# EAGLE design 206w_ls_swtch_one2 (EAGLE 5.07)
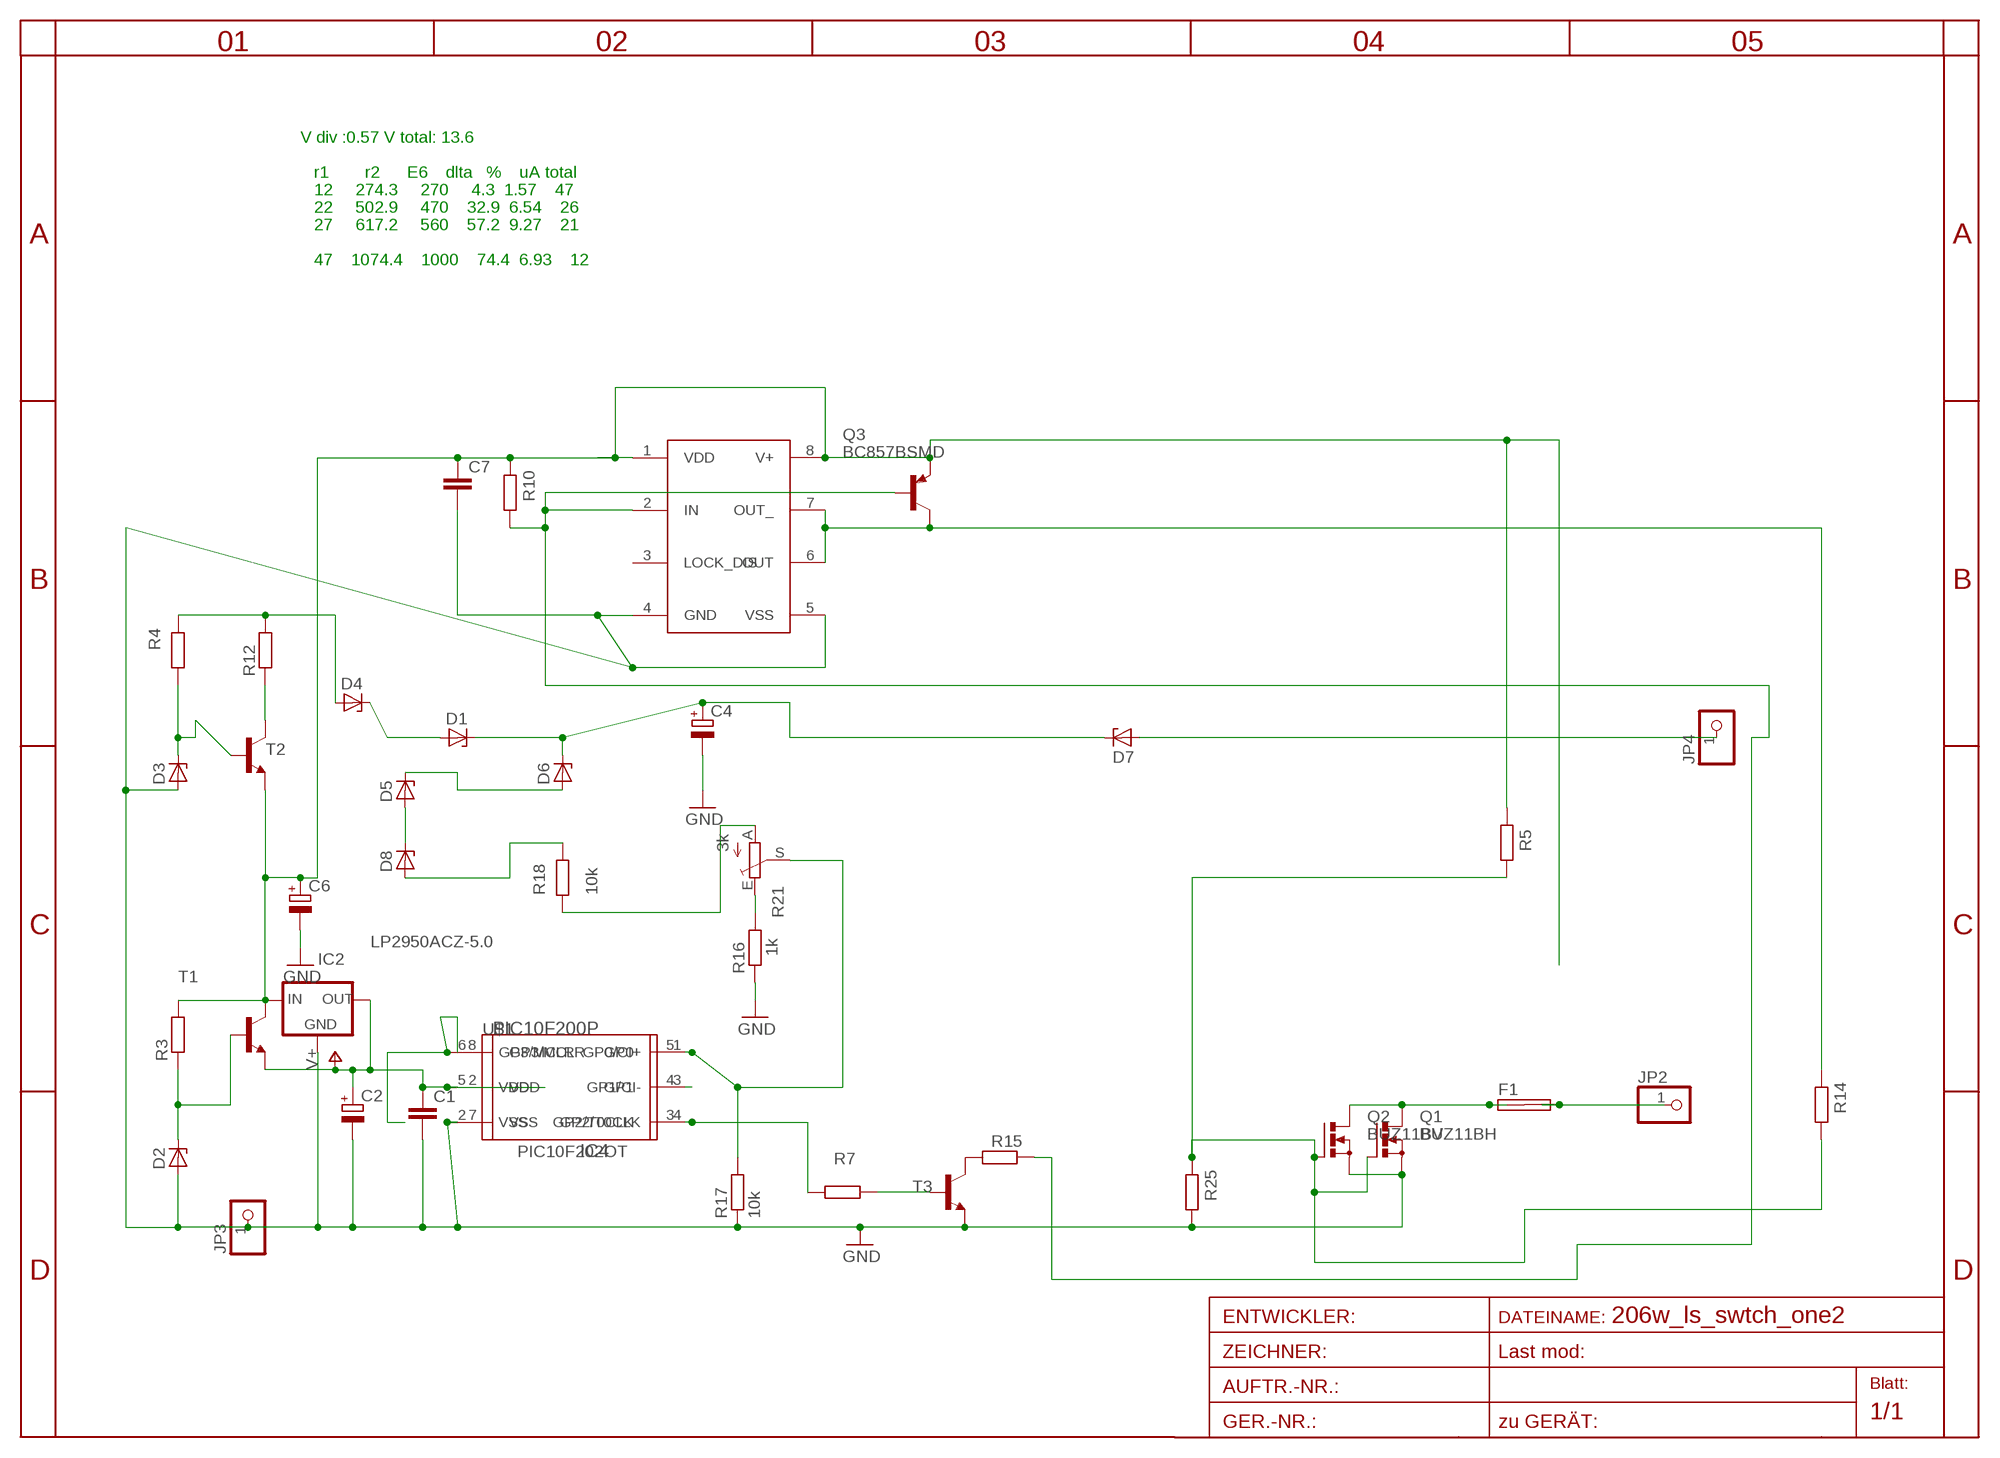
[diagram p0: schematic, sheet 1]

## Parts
C1  C-EUC1206  [C1206]
C2  CPOL-EUSANYO_SMD_E12  [SANYO-OSCON_SMD_E12]
C4  CPOL-EUE5-8.5  [E5-8,5]
C6  CPOL-EUSANYO_SMD_E12  [SANYO-OSCON_SMD_E12]
C7  C-EUC1206  [C1206]
D1  ZENER-DIODESMB  [SMB]
D2  ZENER-DIODESOD80C  [SOD80C]
D3  ZENER-DIODESMB  [SMB]
D4  ZENER-DIODESMB  [SMB]
D5  ZENER-DIODESMB  [SMB]
D6  ZENER-DIODESMB  [SMB]
D7  ZENER-DIODESMB  [SMB]
D8  ZENER-DIODESMB  [SMB]
F1  SHK20L7MM5  [7MM5]
IC2  LP2950ACZ-5.0  [TO92]
IC3  TC4432X  [SO-08]
IC4  PIC10F200P  [DIL8]
JP2  PINHD-1X11MM6  [1X1MM8]
JP3  PINHD-1X11MM6  [1X1MM8]
JP4  PINHD-1X11MM6  [1X1MM8]
Q1  BUZ11BH  [TO220BH]
Q2  BUZ11BV  [TO220BV]
Q3  BC857BSMD  [SOT23-BEC]
R3  R-EU_R0805  [R0805]
R4  R-EU_R0805  [R0805]
R5  R-EU_R0805  [R0805]
R7  R-EU_R0805  [R0805]
R10  R-EU_R0805  [R0805]
R12  R-EU_R0805  [R0805]
R14  R-EU_R0805  [R0805]
R15  R-EU_R0805  [R0805]
R16  1k  R-EU_R0805  [R0805]
R17  10k  R-EU_R0805  [R0805]
R18  10k  R-EU_R1206  [R1206]
R21  3k  TRIM_EU-CA6V  [CA6V]
R25  R-EU_R0805  [R0805]
T1  BC846BLT1-NPN-SOT23-BEC  [SOT23-BEC]
T2  BC846BLT1-NPN-SOT23-BEC  [SOT23-BEC]
T3  BC846BLT1-NPN-SOT23-BEC  [SOT23-BEC]
U$1  PIC10F202OT  [SOT23-6]

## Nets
BB: IC3.2(IN) Q3.B R10.1 R15.2
DRAIN: F1.1A F1.1B Q1.D Q2.D
GND: C1.2 C2.- C4.- C6.- C7.2 D2.A D3.A IC2.2(GND) IC3.4(GND) IC3.5(VSS) IC4.7(VSS) JP3.1 Q1.S Q2.S R16.1 R17.1 R25.1 T3.E U$1.2(VSS)
IN+: D7.A JP4.1
N$1: IC4.5(GP0) R17.2 R21.S U$1.1(GP0/CI+)
N$2: IC4.8(GP3/MCLR) U$1.6(GP3/MCLR)
N$3: Q1.G Q2.G R5.1 R14.1 R25.2
N$4: R18.1 R21.A
N$5: R16.2 R21.E
N$6: D2.C R3.1 T1.B
N$9: IC4.3(GP2/T0CLK) R7.1 U$1.4(GP2/T0CLK)
N$10: D5.C D6.A
N$11: IC3.6(OUT) IC3.7(OUT_) Q3.C R14.2
N$12: D3.C R4.1 T2.B
N$16: R12.1 T2.C
N$17: D5.A D8.C
N$18: D1.A D4.C
N$19: D8.A R18.2
N$21: D4.A R4.2 R12.2
N$25: IC4.4(GP1) U$1.3(GP1/CI-)
N$26: R7.2 T3.B
N$31: R15.1 T3.C
OUT-: F1.2A F1.2B JP2.1
V60: C4.+ D1.C D6.C D7.C
V+: C1.1 C2.+ IC2.1(OUT) IC4.2(VDD) T1.E U$1.5(VDD)
VCC: C6.+ C7.1 IC2.3(IN) IC3.1(VDD) IC3.8(V+) Q3.E R3.2 R5.2 R10.2 T1.C T2.E
Unconnected: IC3.3(LOCK_DIS)

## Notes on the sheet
- V div :0.57 V total: 13.6
- r1        r2      E6    dlta   %    uA total
- 12     274.3     270     4.3  1.57    47
- 22     502.9     470    32.9  6.54    26
- 27     617.2     560    57.2  9.27    21
- 47    1074.4    1000    74.4  6.93    12

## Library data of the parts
C1 C7 = rcl:C-EU: CAPACITOR, European symbol
C2 C4 C6 = rcl:CPOL-EU: POLARIZED CAPACITOR, European symbol
D1-D8 = diode-1:ZENER-DIODE: Z-Diode
F1 = fuse:SHK20L: FUSE HOLDER 5 x 20 mm, SH contact, SHH1 Schukat, E1073 Buerklin
IC2 = v-reg:LP2950?*: Source: http://cache.national.com/ds/LP/LP2950.pdf
IC3 = microchip:TC4432
IC4 = microchip-5:PIC10F20*: uPC nW 0,25/0,5k Program Flash memory
JP2-JP4 = pinhead:PINHD-1X1: PIN HEADER
Q1 Q2 = transistor-power:BUZ11: N-CHANNEL MOS FET
Q3 = transistor-pnp:BC857*: PNP Transistror
R3-R5 R10 R12 R14-R16 R25 = rcl:R-EU_: RESISTOR, European symbol
R7 R17 R18 = rcl-2:R-EU_: RESISTOR, European symbol
R21 = pot:TRIM_EU-: POTENTIOMETER
T1-T3 = transistor-neu-to92:*-NPN-: NPN Transistror
U$1 = microchip-5:PIC10F2*: uPC nW 0,25/0,5k Program Flash memory Comparator

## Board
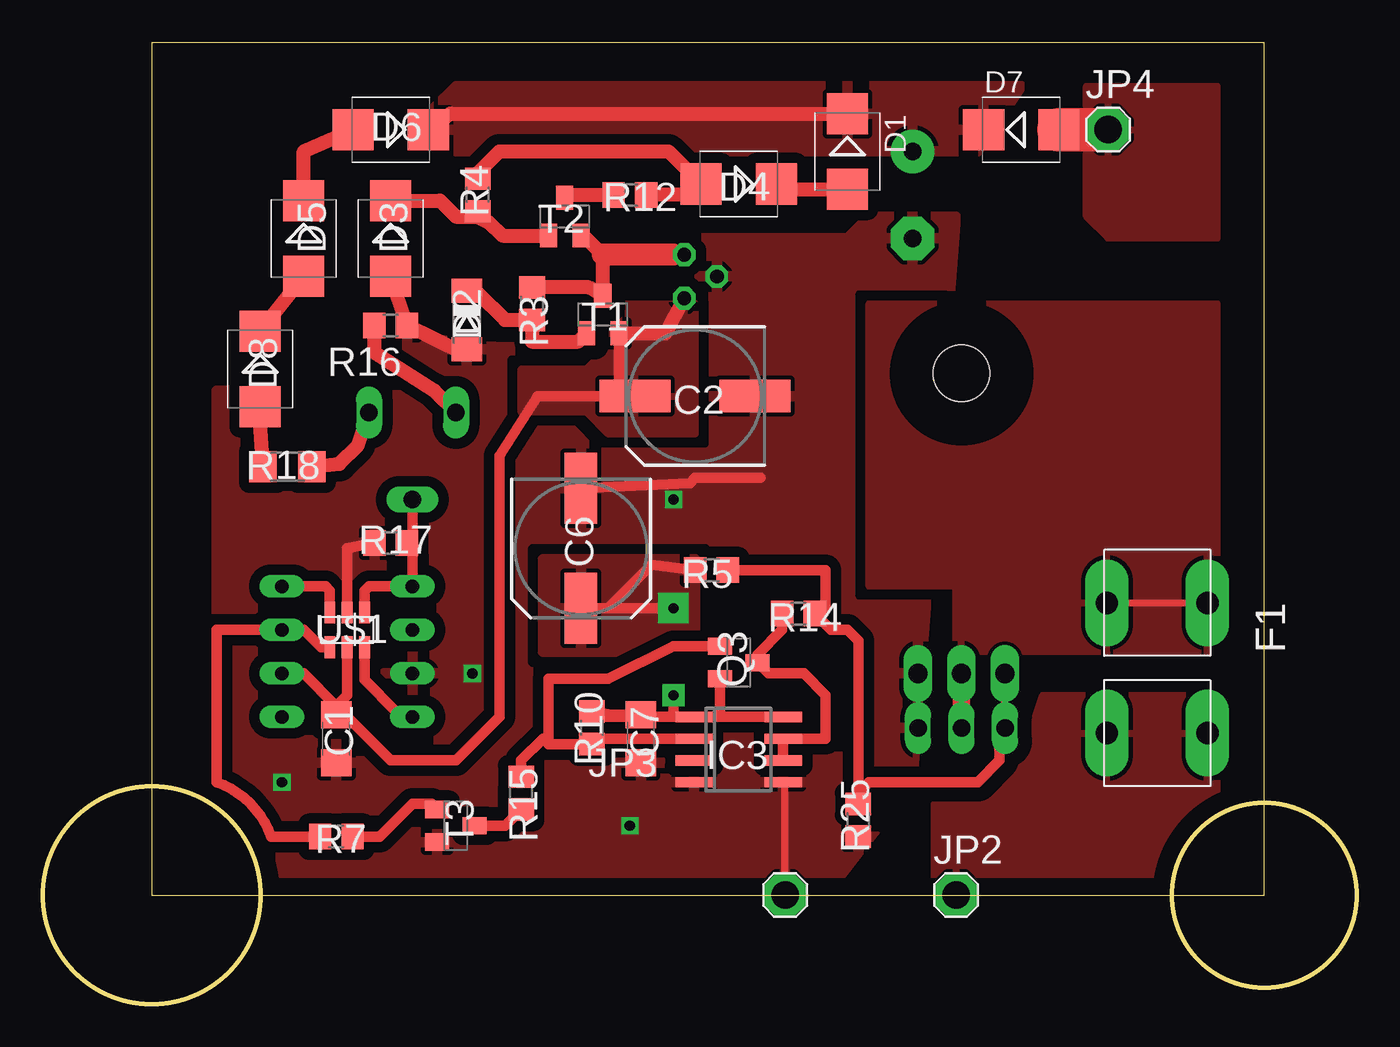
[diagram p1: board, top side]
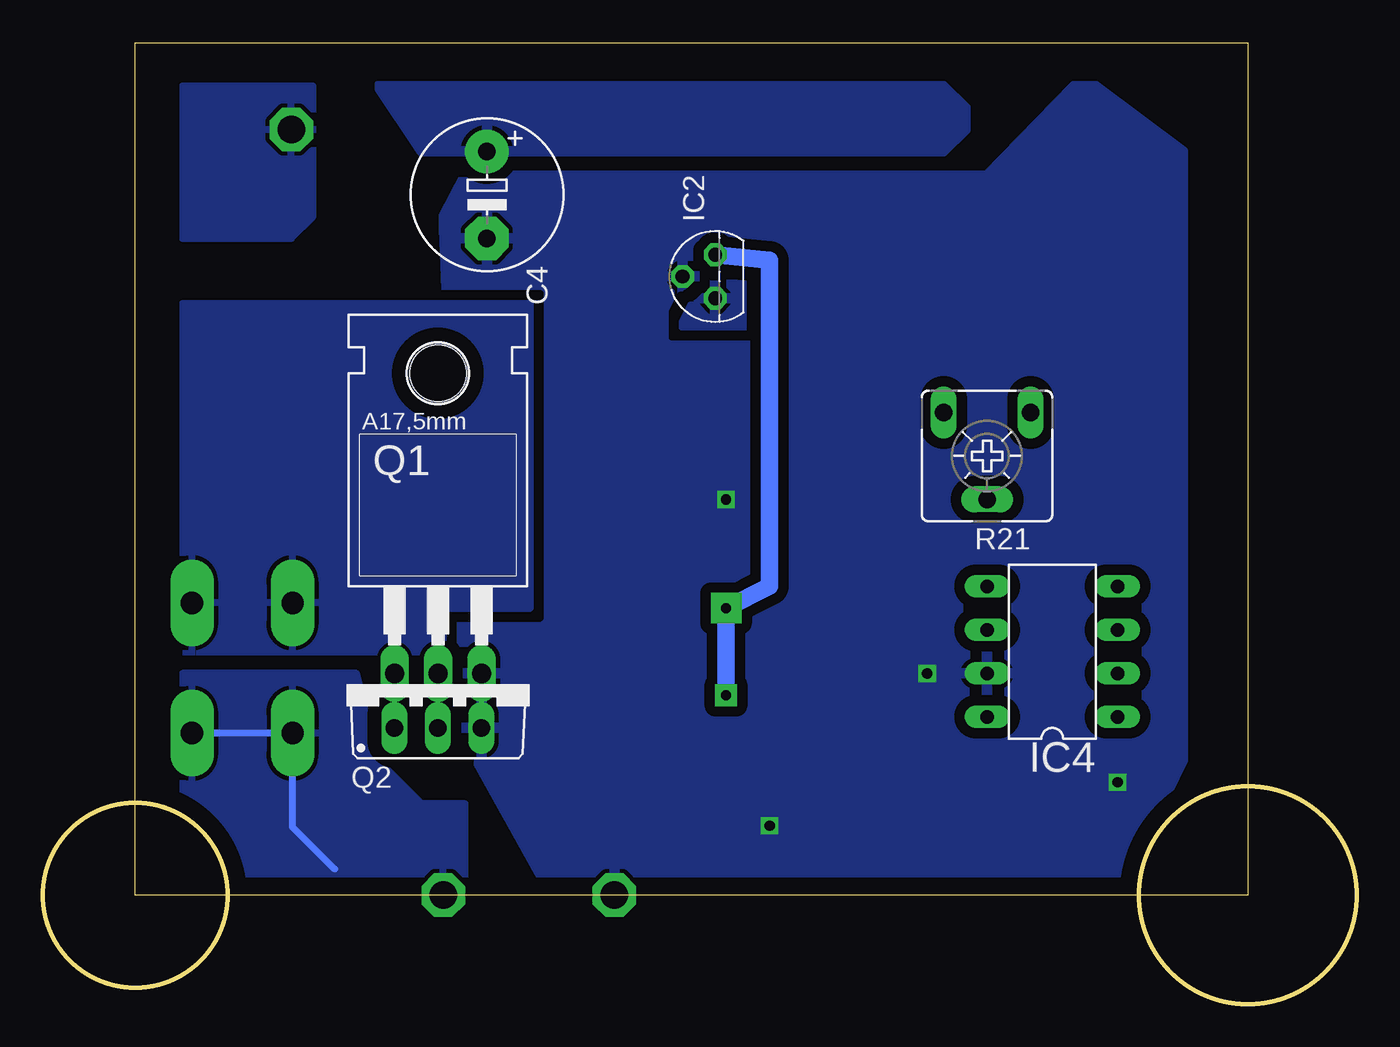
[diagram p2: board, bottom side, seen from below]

Size 76.74 x 56.11 mm. Coordinates in mm from the lower left corner, seen from the top.
Outline: 6.35,6.35 71.35,6.35 71.35,56.11 6.35,56.11 6.35,6.35
Outline: circle at 71.35,6.35 radius 5.39
Outline: circle at 6.35,6.35 radius 6.35
Copper layers (1*16): Top 0.035mm / dielectric 1.5mm / Bottom 0.035mm
Design rules "default": minimum track width 10mil, minimum drill 24mil, track to track 8mil, track to pad 8mil, pad to pad 8mil, via to via 8mil, smd to smd 8mil, copper to edge 40mil, drill to drill 8mil, minimum pad ring 10mil, minimum via ring 8mil, stop-mask expansion 4mil, vias tented up to drill 0mil, thermal gap 10mil

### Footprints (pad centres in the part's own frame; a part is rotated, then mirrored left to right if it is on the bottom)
C1206 = smd 1.6 x 1.8: 1 -1.4,0; 2 1.4,0
SANYO-OSCON_SMD_E12 = smd 4.15 x 1.9: + 3.5,0; - -3.5,0
E5-8,5 = drill 1.016 pad 2.54 round: + -2.54,0 | drill 1.016 pad 2.54 octagon: - 2.54,0
SMB = smd 2.4 x 2.4: A 2.2,0; C -2.2,0
SOD80C = smd 1.4 x 1.8: A 1.7,0; C -1.7,0
7MM5 = drill 1.3 pad 2.54 long: 1A -3.8,2.94; 1B -3.8,-2.94; 2A 3.8,2.94; 2B 3.8,-2.94
TO92 = drill 0.813 octagon: 1 -1.27,0; 2 0,1.905; 3 1.27,0
SO-08 = smd 0.6 x 2.2: 1 -1.905,-2.6; 2 -0.635,-2.6; 3 0.635,-2.6; 4 1.905,-2.6; 5 1.905,2.6; 6 0.635,2.6; 7 -0.635,2.6; 8 -1.905,2.6
DIL8 = drill 0.8 long: 1 -3.81,-3.81; 2 -1.27,-3.81; 3 1.27,-3.81; 4 3.81,-3.81; 5 3.81,3.81; 6 1.27,3.81; 7 -1.27,3.81; 8 -3.81,3.81
1X1MM8 = drill 1.6 pad 2.54 octagon: 1 0,0
TO220BH = drill 1.118 long: D 0,-6.35; G -2.54,-6.35; S 2.54,-6.35 | hole 3.302: 0,11.176
TO220BV = drill 1.016 long: D 0,-2.54; G -2.54,-2.54; S 2.54,-2.54
SOT23-BEC = smd 1 x 1.4: B -0.95,-1.1; C 0,1.1; E 0.95,-1.1
R0805 = smd 1.3 x 1.5: 1 -0.95,0; 2 0.95,0
R1206 = smd 1.6 x 1.803: 1 -1.422,0; 2 1.422,0
CA6V = drill 1.016 long: A -2.54,-2.54; E 2.54,-2.54; S 0,2.54
SOT23-6 = smd 0.635 x 1.27: 1 -1.016,-1.016; 2 0,-1.016; 3 1.016,-1.016; 4 1.016,1.016; 5 0,1.016; 6 -1.016,1.016

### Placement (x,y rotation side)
C1  17.14,15.48 270 top
C2  38.1,35.48 180 top
C4  50.8,47.23 270 bottom
C6  31.43,26.59 270 top
C7  34.92,15.48 270 top
D1  46.99,49.77 270 top
D2  24.77,39.93 270 top
D3  20.32,44.69 270 top
D4  40.64,47.87 180 top
D5  15.24,44.69 270 top
D6  20.32,51.04 180 top
D7  57.15,51.04 0 top
D8  12.7,37.07 270 top
F1  65.09,19.61 270 top
IC2  37.46,42.47 90 bottom
IC3  40.64,14.85 270 top
IC4  17.78,20.56 90 bottom
JP2  53.35,6.35 0 top
JP3  43.35,6.35 0 top
JP4  62.23,51.04 0 top
Q1  53.66,25.64 0 bottom
Q2  53.66,18.66 0 bottom
Q3  40.64,19.92 270 top
R3  28.58,40.88 90 top
R4  25.4,47.23 90 top
R5  39.05,25.32 180 top
R7  17.14,9.76 0 top
R10  32.07,16.12 90 top
R12  34.29,47.23 0 top
R14  44.13,22.78 180 top
R15  27.94,12.3 90 top
R16  20.32,39.61 180 top
R17  20.32,26.91 0 top
R18  14.29,31.36 180 top
R21  21.59,31.99 180 bottom
R25  47.62,10.72 90 top
T1  32.7,40.25 0 top
T2  30.48,45.96 0 top
T3  24.13,10.4 270 top
U$1  17.78,21.83 180 top

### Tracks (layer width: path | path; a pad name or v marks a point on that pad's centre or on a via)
BB
  Top 0.61: Q3.B 36.83,20.88 33.02,18.97 29.53,18.97 29.53,15.48 | 29.53,15.48 29.53,15.16 R10.1 32.38,15.48 IC3.2 | R15.2 27.94,14.21 29.21,15.48 29.53,15.48
DRAIN
  Top 0.406: F1.1B F1.1A
  Top 1.016: Q2.D Q1.D
  pour Top: 48.26,40.88 68.58,40.88 68.58,20.56 53.34,20.56 53.34,24.37 48.26,24.37
  pour Bottom: 48.26,40.88 68.58,40.88 68.58,20.56 53.34,20.56 53.34,23.1 48.26,23.1
GND  (via drill 0.6)
  Top 0.406: JP3.1 43.35,12.83 IC3.5
  Top 0.61: C6.- 37.79,30.41 38.1,30.72 41.91,30.72 | U$1.2 17.78,26.59 R17.1
  Top 0.813: D3.A R16.1 24.56,38.02 D2.A
  other vias: 34.29,10.4 36.83,29.45 13.97,12.94 25.08,19.29
  pour Top (isolate 0.61, rank 3): 26.67,38.34 16.51,39.61 16.51,35.8 10.16,35.8 10.16,12.94 13.97,6.35 45.72,6.35 50.8,12.94 53.34,45.96 48.26,45.96 46.99,44.69 34.29,44.69 31.75,38.34
  pour Bottom (isolate 0.61, rank 3): 16.51,53.58 15.24,53.58 10.16,49.77 10.16,14.21 13.97,6.35 46.99,6.35 52.07,15.48 53.34,45.96 52.07,48.35 21.59,48.35
IN+
  Top 2.54: D7.A JP4.1
  pour Top (isolate 0.813): 60.96,53.58 68.58,53.58 68.58,44.69 62.23,44.69 60.96,45.96
  pour Bottom (isolate 0.813): 60.96,53.58 68.58,53.58 68.58,44.69 62.23,44.69 60.96,45.96
N$1
  Top 0.61: U$1.1 18.8,24.12 19.05,24.37 IC4.5 21.59,26.91 | 21.59,26.91 R21.S | 21.59,26.91 R17.2
N$2
  Top 0.61: U$1.6 18.8,18.91 20.64,17.07 21.27,17.07 IC4.8
N$3
  Top 0.406: Q2.G Q1.G
  Top 0.61: R5.1 45.72,25.32 45.72,23.1 45.08,23.1 R14.1 46.04,21.83 46.99,21.83 47.62,21.2 R25.2 47.62,12.3 48.26,12.94 54.61,12.94 55.88,14.21 55.88,15.8 Q2.G
N$4
  Top 0.813: R18.1 17.31,31.52 18.41,32.62 R21.A
N$5
  Top 0.813: R16.2 19.37,38.02 22.86,35.8 R21.E
N$6
  Top 0.813: D2.C 24.88,41.52 25.4,41.52 26.98,39.93 R3.1 28.58,38.66 31.27,38.66 T1.B
N$9
  Top 0.61: U$1.4 16.26,20.81 15.24,21.83 IC4.3 10.16,21.83 10.16,12.94 arc-51 13.34,9.76 R7.1
N$10
  Top 0.813: D6.A 15.24,49.77 D5.C
N$11
  Top 0.61: IC3.6 IC3.7 45.72,15.48 45.72,18.02 44.45,19.29 42.38,19.29 Q3.C 41.74,20.39 43.18,21.83 R14.2
N$12
  Top 0.813: D3.C 23.2,46.89 24.13,45.96 25.4,45.96 | T2.B 26.84,44.86 26.03,45.64 25.4,45.96 | 25.4,45.96 R4.1
N$16
  Top 0.813: R12.1 30.48,47.23 T2.C
N$17
  Top 0.813: D8.C D5.A
N$18
  Top 0.61: D4.C 43.13,47.57
  Top 0.813: 43.13,47.57 D1.A
N$19
  Top 0.813: D8.A 12.7,33.9 R18.2
N$21
  Top 0.813: R4.2 25.4,48.5 26.67,49.77 36.53,49.77 D4.A 37.8,47.23 R12.2
N$25
  Top 0.61: U$1.3 16.76,24.12 16.51,24.37 IC4.4
N$26
  Top 0.406: 22.71,11.67 T3.B
  Top 0.61: R7.2 19.69,9.76 21.59,11.67 22.71,11.67
N$31
  Top 0.61: T3.C 26.98,10.4 R15.1
OUT-
  Bottom 0.406: F1.2A F1.2B 62.15,10.32 59.69,7.86
  pour Top (isolate 0.813): 58.42,18.02 68.58,18.02 68.58,6.59 52.07,6.59 52.07,11.67 54.61,11.67 57.15,14.21
  pour Bottom (isolate 0.813): 58.42,19.29 68.58,19.29 68.58,18.02 68.58,6.59 52.07,6.59 52.07,11.67 54.61,11.67 57.15,14.21
V60
  Top 0.813: D1.C 23.79,51.97 D6.C
  pour Top (isolate 0.61): 57.15,53.58 24.13,53.58 22.86,52.31 22.86,51.04 24.13,49.77 54.61,49.77
  pour Bottom (isolate 0.61): 57.15,53.58 24.13,53.58 22.86,52.31 22.86,51.04 24.13,49.77 54.61,49.77
V+
  Top 0.406: 33.65,36.44 34.29,35.8 34.29,35.79 C2.+ | 17.78,16.75 17.27,16.75 C1.1
  Top 0.61: 17.14,17.38 C1.1 | 17.14,17.38 15.24,19.29 IC4.2 | U$1.5 17.78,18.02 17.14,17.38 | 33.65,36.44 T1.E | C2.+ 28.89,35.48 26.67,31.99 26.67,16.75 24.13,14.21 20.32,14.21 17.78,16.75
  Top 0.813: T1.E 36.37,39.15 IC2.1
  pour Bottom (isolate 0.813): 35.56,42.15 38.1,42.15 39.37,39.61 35.56,39.61
  pour Top (isolate 0.813): 36.83,40.88 38.1,40.88 38.1,33.26 33.02,33.26 31.75,34.53 27.94,34.53 27.94,37.07 31.75,37.07 33.02,38.34 33.02,40.88
VCC  (via drill 0.6 pad 1.27, 0.6 pad 1.78)
  Top 0.61: Q3.E 39.54,16.9 39.69,16.75 | 41.27,16.75 IC3.8 39.69,16.75 | 39.69,16.75 IC3.1 36.83,16.75 | 36.83,16.75 31.88,16.75 C7.1 33.2,16.88 R10.2 | R5.2 35.56,25.64 33.02,23.1 | 32.06,23.1 C6.+ 31.75,23.1 32.06,23.1 | v36.83,23.1 33.02,23.1 | 36.83,16.75 v36.83,18.02 | 33.02,23.1 32.06,23.1 | IC2.3 36.83,43.74
  Top 0.813: T2.E 31.58,44.86 32.7,43.74 T1.C 31.9,41.83 R3.2
  Top 1.27: 36.83,43.74 32.7,43.74
  Bottom 1.016: v36.83,18.02 v36.83,23.1 34.29,24.37 34.29,43.42 IC2.3
  pour Top (isolate 0.61): 29.21,25.96 38.1,25.96 38.1,21.83 34.29,20.56 29.21,20.56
